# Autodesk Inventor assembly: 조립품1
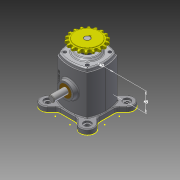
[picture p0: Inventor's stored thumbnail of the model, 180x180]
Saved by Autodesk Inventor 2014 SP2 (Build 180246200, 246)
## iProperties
Created: 2016-05
Part Number: 조립품1
Document SubType Name: Assembly
Designer: 달님반
Author: 달님반
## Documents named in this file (11)
- C:\Users\달님반\Desktop\정무근\조립품1.iam
- C:\Users\달님반\Desktop\정무근\460507V1002.ipt
- C:\Users\달님반\Desktop\정무근\M4x0.7x12.ipt
- C:\Users\달님반\Desktop\정무근\베어링-6203.ipt
- C:\Users\달님반\Desktop\정무근\부시.ipt
- C:\Users\달님반\Desktop\정무근\스프로킷.ipt
- C:\Users\달님반\Desktop\정무근\슬라이더.ipt
- C:\Users\달님반\Desktop\정무근\편심축.ipt
- C:\Users\달님반\Desktop\정무근\키5x5.ipt
- C:\Users\달님반\Desktop\정무근\오일실.ipt
- C:\Users\달님반\Desktop\정무근\커버.ipt
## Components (8 placed, 2 different names)
1. 460507V1002:1
2. M4x0.7x12:1
3. M4x0.7x12:9
4. M4x0.7x12:11
5. M4x0.7x12:2
6. M4x0.7x12:3
7. M4x0.7x12:4
8. M4x0.7x12:5
